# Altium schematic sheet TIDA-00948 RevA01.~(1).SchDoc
size 431 x 279 mm; Date: Not shown in title block; ApprovedBy: Not shown in title block; CheckedBy: Not shown in title block; Author: Not shown in title block; CompanyName: Not shown in title block; Engineer: Not shown in title block; Organization: Not shown in title block; Address1: Not shown in title block; Address2: Not shown in title block; Address3: Not shown in title block; Address4: Not shown in title block; DocumentNumber: 1; Revision: Use project parameter SCH_Rev; SheetNumber: 2; SheetTotal: 3; PageSetup: Record=PageOptions¦CenterHorizontal=True¦CenterVertical=True¦PrintScale=1.00¦XCorrection=1.00¦YCorrection=1.00¦PrintKind=0¦BorderSize=5000000¦LeftOffset=0¦BottomOffset=0¦Orientation=2¦PaperLength=1000¦PaperWidth=1000¦Scale=100¦PaperSource=15¦PrintQuality=600¦MediaType=1¦DitherType=10¦PaperKind=Letter¦PrintScaleMode=1
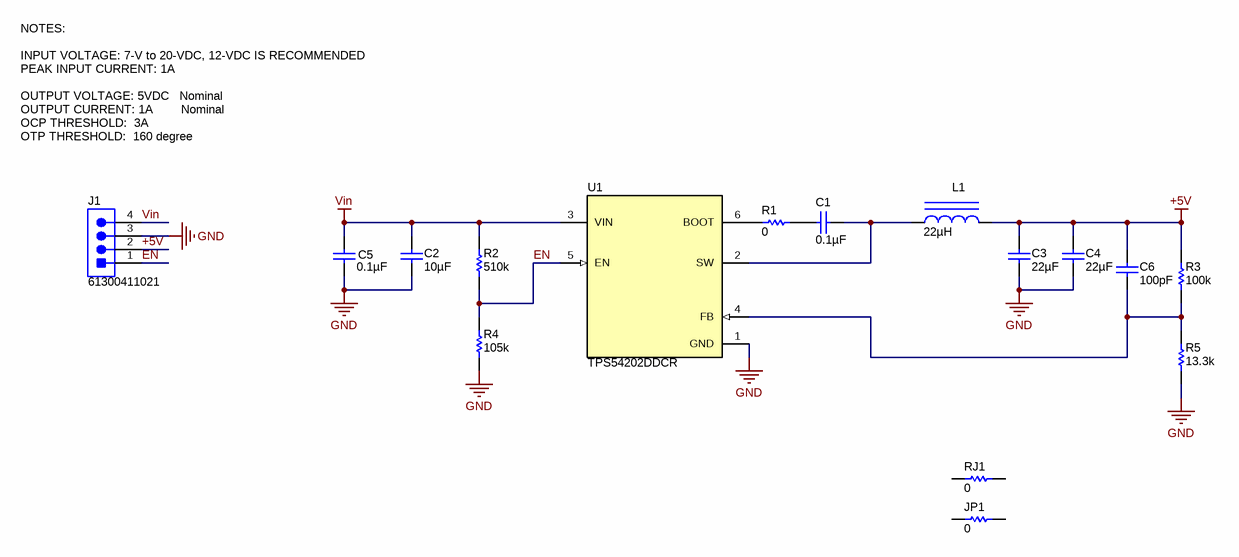
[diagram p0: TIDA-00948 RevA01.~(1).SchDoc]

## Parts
C1  ValueDisplayed: 0.1µF  [C/0805/SMT1]  (hidden comment: GRM188R71E104KA01D)
C2  ValueDisplayed: 10µF  [1206]  (hidden comment: GRM31CR71E106KA12L)
C3  ValueDisplayed: 22µF  [1206_190]  (hidden comment: GCM31CR71A226KE02)
C4  ValueDisplayed: 22µF  [1206_190]  (hidden comment: GCM31CR71A226KE02)
C5  ValueDisplayed: 0.1µF  [0603]  (hidden comment: GRM188R71E104KA01D)
C6  ValueDisplayed: 100pF  [C/0805/SMT1]  (hidden comment: 06033C101KAT2A)
J1  61300411021  [Wurth_61300411021]
JP1  ValueDisplayed: 0  [JUMP-5]  (hidden comment: CRCW0603100KFKEA)
L1  ValueDisplayed: 22µH  [LPS8045B]  (hidden comment: LPS8045B-333MRB)
R1  ValueDisplayed: 0  [0603]  (hidden comment: CRCW06030000Z0EA)
R2  ValueDisplayed: 510k  [0603]  (hidden comment: CRCW0603510KJNEA)
R3  ValueDisplayed: 100k  [R/0805/SMT1]  (hidden comment: CRCW0603100KFKEA)
R4  ValueDisplayed: 105k  [0603]  (hidden comment: CRCW0603105KFKEA)
R5  ValueDisplayed: 13.3k  [0603]  (hidden comment: CRCW060313K3FKEA)
RJ1  ValueDisplayed: 0  [R/0805/SMT1]  (hidden comment: CRCW0603100KFKEA)
U1  TPS54202DDCR  [DDC0006A_N]

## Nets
+5V: C3.1 C4.1 C6.1 J1.2 L1.2 R3.2
GND: C2.2 C3.2 C4.2 C5.2 J1.3 R4.1 R5.1 U1.1(GND)
Vin: C2.1 C5.1 J1.4 R2.2 U1.3(VIN)
EN: J1.1 R2.1 R4.2 U1.5(EN)
NetC1_1: C1.1 R1.2
NetC1_2: C1.2 L1.1 U1.2(SW)
NetC6_2: C6.2 R3.1 R5.2 U1.4(FB)
NetR1_1: R1.1 U1.6(BOOT)

Not connected (* = marked no-connect by the designer): JP1 1 2; RJ1 1 2

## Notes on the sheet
- NOTES:
  INPUT VOLTAGE: 7-V to 20-VDC, 12-VDC IS RECOMMENDED
  PEAK INPUT CURRENT: 1A
  OUTPUT VOLTAGE: 5VDC   Nominal
  OUTPUT CURRENT: 1A        Nominal
  OCP THRESHOLD:  3A
  OTP THRESHOLD:  160 degree

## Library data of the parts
C1 = GRM188R71E104KA01D: CAP, CERM, 0.1 µF, 25 V, +/- 10%, X7R, 0603; Manufacturer: MuRata; Polarized: N; CompType: Capacitor; Value: 0.1uF; U/M: EA; Cap_F: 0.0000001; Tolerance_%: 10; Value1: Unknown; VDC_V: 25; Value2: 25V; TaMin_C: -55; TaMax_C: 125; Cap_Case: 0603; AEC Category: Q200
C2 = GRM31CR71E106KA12L: CAP, CERM, 10 µF, 25 V, +/- 10%, X7R, 1206; Manufacturer: MuRata; Polarized: N; CompType: Capacitor; Value: 10uF; U/M: EA; Cap_F: 0.00001; Tolerance_%: 10; Value1: Unknown; VDC_V: 25; Value2: 25V; TaMin_C: -55; TaMax_C: 125; Cap_Case: 2220; AEC Category: Q200
C3 C4 = GCM31CR71A226KE02: CAP, CERM, 22 µF, 10 V, +/- 10%, X7R, AEC-Q200 Grade 1, 1206_190; Manufacturer: MuRata; Polarized: N; CompType: Capacitor; Value: 22uF; U/M: EA; Cap_F: 0.000022; Tolerance_%: 10; Value1: Unknown; Value2: 10V; TaMin_C: -55; TaMax_C: 125; Cap_Case: 1206; AEC Category: Q200; AEC Qualified: Y; AEC Grade: 1
C5 = GRM188R71E104KA01D: CAP, CERM, 0.1 µF, 25 V, +/- 10%, X7R, 0603; Manufacturer: MuRata; Polarized: N; CompType: Capacitor; Value: 0.1uF; U/M: EA; Cap_F: 0.0000001; Tolerance_%: 10; Value1: Unknown; VDC_V: 25; Value2: 25V; TaMin_C: -55; TaMax_C: 125; AEC Category: Q200
C6 = 06033C101KAT2A: CAP, CERM, 100 pF, 25 V, +/- 10%, X7R, 0603; Manufacturer: AVX; Polarized: N; CompType: Capacitor; Value: 100pF; U/M: EA; Cap_F: 0.0000000001; Tolerance_%: 10; Value1: Unknown; VDC_V: 25; Value2: 25V; TaMin_C: -55; TaMax_C: 125; Cap_Case: 0603; AEC Category: Q200
J1 = 61300411021: Header, 2.54 mm, 4x1, Gold, R/A, TH; Manufacturer: Wurth Elektronik; SymbolCreator: a0412235; Pitch_mm: 2.54; Gender: Male; Shrouded: N; Row_Count: 1
JP1 R3 RJ1 = CRCW0603100KFKEA: RES, 100 k, 1%, 0.1 W, 0603; Manufacturer: Vishay-Dale; CompType: Resistor; Value: 100k; Res_ohm: 100000; Tolerance_%: 1; Power_W: 0.1; Value2: 0.1W; VDC_V: 75; TempCo: 100 ppm/C; EIA_Code: E96; U/M: EA; AEC Category: Q200
L1 = LPS8045B-333MRB: Inductor, Shielded, Ferrite, 33 µH, 1.2 A, 0.121 ohm, SMD; Manufacturer: Coilcraft; Value: 33uH; Ind_H: 33.0E-6; Imax_A: 1.2; Irms: 1.2A @ 20C rise; Isat: 1.8A @ 10% inductance drop; DCR_ohm: 0.121; Value2: 1.2A; AEC Category: Q200; AEC Qualified: N
R1 = CRCW06030000Z0EA: RES, 0, 5%, 0.1 W, 0603; Manufacturer: Vishay-Dale; CompType: Resistor; Value: 0; Value_Code: 0000; Tolerance_%: 5; Power_W: 0.1; Value2: 0.1W; VDC_V: 75; TempCo: 200 ppm/C; EIA_Code: E24; U/M: EA; AEC Category: Q200
R2 = CRCW0603510KJNEA: RES, 510 k, 5%, 0.1 W, 0603; Manufacturer: Vishay-Dale; CompType: Resistor; Value: 510k; Res_ohm: 510000; Tolerance_%: 5; Power_W: 0.1; Value2: 0.1W; VDC_V: 75; TempCo: 200 ppm/C; EIA_Code: E24; U/M: EA; AEC Category: Q200
R4 = CRCW0603105KFKEA: RES, 105 k, 1%, 0.1 W, 0603; Manufacturer: Vishay-Dale; CompType: Resistor; Value: 105k; Res_ohm: 105000; Tolerance_%: 1; Power_W: 0.1; Value2: 0.1W; VDC_V: 75; TempCo: 100 ppm/C; EIA_Code: E96; U/M: EA; AEC Category: Q200
R5 = CRCW060313K3FKEA: RES, 13.3 k, 1%, 0.1 W, 0603; Manufacturer: Vishay-Dale; CompType: Resistor; Value: 13.3k; Res_ohm: 13300; Value_Code: 13k3; Tolerance_%: 1; Power_W: 0.1; Value2: 0.1W; VDC_V: 75; TempCo: 100 ppm/C; EIA_Code: E96; U/M: EA; AEC Category: Q200
U1 = TPS54202DDCR: 4.5-V TO 28-V INPUT, 2-A OUTPUT, EMI FRIENDLY SYNCHRONUOUS STEP-DOWN CONVERTOR, DDC0006A; Alternate PartNumber: TPS54202DDCT; Manufacturer: Texas Instruments; SymbolCreator: a0411947; CompType: IC; U/M: EA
